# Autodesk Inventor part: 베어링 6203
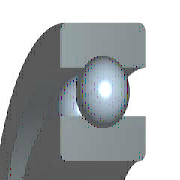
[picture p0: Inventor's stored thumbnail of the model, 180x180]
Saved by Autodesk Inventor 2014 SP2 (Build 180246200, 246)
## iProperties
IsCustomPart: 1
Created: 2015-09
Part Number: 베어링 6203
Material: 강철, 연강
Description: 깊은 그루브 볼 베어링
Document SubType Name: Modeling
Standard: KS B 2023
Standards Organization: KS
Language: ko-KR
Size Designation: 6203 - 17 x 40 x 12
Categories: <MemberInstance><Categories><Category DisplayName="샤프트 부품" InternalName="7f7aeb1f-a693-4053-b835-cee3144e0d98" Mnemonic="SHFT"><Category DisplayName="베어링" Inter
Density: 1 g/cm^3
Appearance: 강철
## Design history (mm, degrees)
sketch "스케치" dims "d0" = 5.98 (= -0.26 x WD + 0.26 x BD)
  geometry: L1 (3.01, 14.25)-(8.99, 14.25); L2 (6, 14.25)-(6, 11.26); L3 (6, 14.25)-(6, 17.24); L4 (3.778, 12.249)-(0, 12.249); L5 (0, 8.5)-(12, 8.5); L6 (3.778, 16.251)-(0, 16.251); L7 (0, 20)-(12, 20); L8 (12, 8.5)-(12, 12.249); L9 (8.222, 12.249)-(12, 12.249); L10 (8.222, 16.251)-(12, 16.251); L11 (12, 20)-(12, 16.251); L12 (-1.4, 0)-(8.4, 0) reference; L13 (0, -0.3)-(0, 5.3) reference
  constraints: 22 end point, 4 point on line, 2 collinear, 2 perpendicular, 2 symmetric about line, 1 midpoint, 1 parallel, 14 other
  dimensions: "d9" = 17 diameter of L5 L12 (= WD); "d11" = 40 diameter of L7 L12 (= BD); "d12" = 12 distance between parallel lines of L8 L13 (= KB); "d13" = 24.498 diameter of L9 L12 (= 0.326 x BD + 0.674 x WD)
revolve "본체" stored, may be unused: angle "d6" = 90 deg
revolve "볼" stored, may be unused: angle "d7" = 90 deg
pattern_circular "IDS_ARRAYBALL[SIMPL:T]" dims angle "d3" = 360 deg
body "Solid1"
fillet "모깎기1" dims "d1" = 0.6 (= KRS)
other parameters: "WD" = 17 [user parameter; used in 5 equation terms], "BD" = 40 [user parameter; used in 5 equation terms], "KB" = 12 [user parameter; used in 1 equation term], "KRS" = 0.6 [user parameter; used in 1 equation term], "d4" = 0, "d5" = 0, "d8" = 0, "d14" = 0, "d15" = 0, "BBA" = 0 [user parameter], "BC0" = 4750000 [user parameter], "BC" = 9560000 [user parameter], "WR" = 8.5 (= 0.5 x WD) [user parameter]
